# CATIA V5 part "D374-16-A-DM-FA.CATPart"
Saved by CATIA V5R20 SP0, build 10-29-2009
Part number: D374-16-A-DM-FA
Bounding box of the stored display mesh (mm): x -14 to 0.35, y -8 to 8, z -8 to 8
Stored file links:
  C:\Users\Utente\Desktop\IO LAVORO\3D X SITO CF\X SITO\PLASTICA\D374\D374-16-A-DM-FA.CATPart
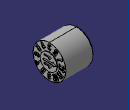
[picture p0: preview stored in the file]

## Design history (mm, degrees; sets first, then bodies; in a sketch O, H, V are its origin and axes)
Set1
  DatumSurface1 to DatumSurface222 "D374-16-A-DM-FA"
Body1 (main body)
